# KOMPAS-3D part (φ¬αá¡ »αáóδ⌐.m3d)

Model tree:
1. Эскиз:1
2. Операция выдавливания:1
     Расстояние 1 = 1; Расстояние 2 = 3.7
3. Эскиз:2
4. Операция выдавливания:2
     Расстояние 1 = 0.5; Расстояние 2 = 3.7
5. Эскиз:3
6. Операция выдавливания:3
     Расстояние 1 = 4.8; Расстояние 2 = 3.7
7. Скругление:1
     Радиус = 1
8. Эскиз:4
9. Операция выдавливания:4
     Расстояние 1 = 0.3
10. Массив по сетке:1  (with: Операция выдавливания:4)  (labels: Экземпляр ( 1, 1 ); Экземпляр ( 2, 1 ); Экземпляр ( 3, 1 ); Экземпляр ( 4, 1 ))
     N 1 = 46; Шаг 1 = 8; Угол раствора = 90; N 2 = 1; Номер 1 = 1; Номер 2 = 1
11. Зеркальное отражение:2

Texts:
  Сплав АЛ8  ГОСТ 1583-93
  stalker61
